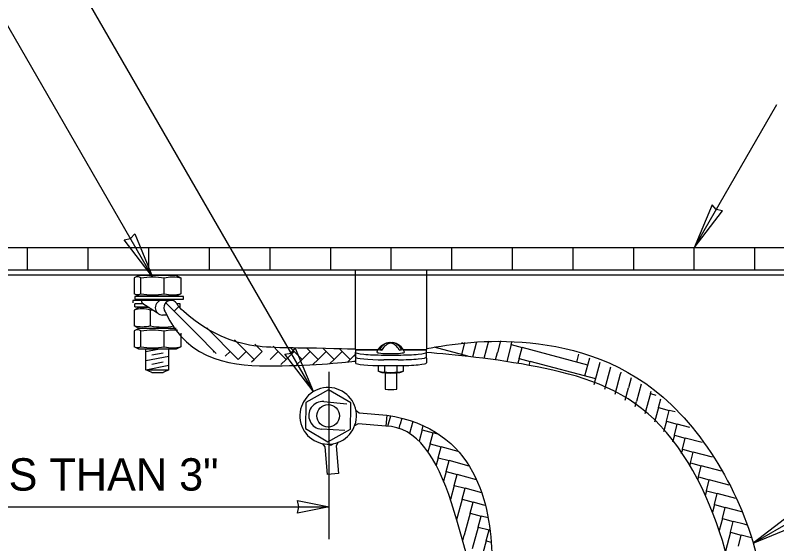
# Model space of a CAD drawing. Extents: x 99862 to 104211, y 98939 to 102076.
# Drawn here: x 100753.9 to 101130.8, y 100589.4 to 100850.7 of the extents above; entities that cross this region are included whole.
import ezdxf

# ---------------------------------------------------------------- set-up
doc = ezdxf.new("R2010")
doc.units = 0
for name, color, linetype in [('Level 1', 7, 'Continuous'), ('Level 11', 7, 'Continuous'), ('Level 15', 7, 'Continuous'), ('Level 20', 7, 'Continuous'), ('Level 22', 7, 'Continuous'), ('Level 3', 7, 'Continuous'), ('Level 4', 7, 'Continuous'), ('Level 6', 7, 'Continuous'), ('Level 8', 7, 'Continuous'), ('Level 9', 7, 'Continuous')]:
    doc.layers.add(name, color=color, linetype=linetype)

msp = doc.modelspace()

# ---------------------------------------------------------------- linework, layer by layer
at = {"layer": 'Level 1'}
for p, q in [((100609.83, 100722.28), (100942.61, 100722.28)), ((100941.81, 100722.28), (101395.03, 100722.28))]:
    msp.add_line(p, q, dxfattribs=at)
at = {"layer": 'Level 11'}
for p, q in [((100935.5, 100685.41), (100934.2, 100685.32)), ((100943.84, 100685.41), (100945.13, 100685.32)), ((100936.9, 100673.89), (100936.9, 100665.89)), ((100942.77, 100665.89), (100942.77, 100673.89))]:
    msp.add_line(p, q, dxfattribs=at)
for start, end in [(78.6144, 160.1915), (19.8085, 84.0285)]:
    msp.add_arc((100939.67, 100681.62), 7.26, start, end, dxfattribs=at)
for centre, major_axis, ratio, start_param, end_param in [((100939.08, 100681.7), (-0.98, -7.12), 0.811046, 3.337919, 4.294117), ((100940.24, 100681.55), (0.98, 7.12), 0.811046, 0.266133, 1.152722), ((100939.09, 100681.55), (-0.98, 7.12), 0.811046, 5.130463, 6.017052), ((100940.25, 100681.7), (0.98, -7.12), 0.811046, 1.989068, 2.945267), ((100939.67, 100684.06), (-6.83, 0), 0.097506, 6.248079, 7.853982), ((100939.67, 100685.58), (6.07, 0), 0.097506, 3.592518, 3.924478), ((100939.67, 100684.06), (-6.83, 0), 0.097506, 1.570796, 3.176699), ((100939.67, 100685.58), (-6.07, 0), 0.097506, 2.358707, 2.690667), ((100939.83, 100665.89), (-2.93, 0), 0.097506, 6.283185, 9.424778)]:
    msp.add_ellipse(centre, major_axis=major_axis, ratio=ratio, start_param=start_param, end_param=end_param, dxfattribs=at)
at = {"layer": 'Level 15'}
for p, q in [((100901.25, 100664.76), (100759.32, 100910.59)), ((100821.85, 100721.4), (100748.39, 100848.63)), ((101089.96, 100735.77), (101130.81, 100806.52)), ((100909.25, 100591.65), (100909.25, 100674.45)), ((101119.16, 100589.63), (101175.45, 100622.13)), ((100609.83, 100607.65), (100909.25, 100607.65))]:
    msp.add_line(p, q, dxfattribs=at)
for points in [[(101089.96, 100735.77), (101103.96, 100754.04), (101100.85, 100754.62), (101098.79, 100757.03)], [(100821.85, 100721.4), (100807.85, 100739.68), (100810.96, 100740.26), (100813.02, 100742.66)], [(100901.25, 100664.76), (100887.25, 100683.04), (100890.36, 100683.62), (100892.42, 100686.03)], [(100909.25, 100607.65), (100893.52, 100604.57), (100894.25, 100607.65), (100893.52, 100610.74)], [(101119.16, 100589.63), (101140.42, 100598.46), (101138.01, 100600.52), (101137.44, 100603.63)]]:
    msp.add_lwpolyline(points, close=True, dxfattribs=at)
at = {"layer": 'Level 22'}
msp.add_arc((100908.75, 100652.63), 14.01, 9.587, 9.5761, dxfattribs=at)
at = {"layer": 'Level 3'}
for p, q in [((100609.93, 100724.78), (101689.72, 100724.79)), ((100813.01, 100706.56), (100813.01, 100707.99)), ((100817.37, 100707.99), (100813.01, 100707.99)), ((100835.49, 100707.99), (100834, 100707.99)), ((100835.49, 100706.56), (100835.49, 100707.99)), ((100818.54, 100675.44), (100818.54, 100685.55)), ((100829.94, 100675.44), (100829.94, 100685.55)), ((100818.54, 100675.44), (100829.94, 100675.44)), ((100821.39, 100674.02), (100827.09, 100674.02))]:
    msp.add_line(p, q, dxfattribs=at)
msp.add_lwpolyline([(100837.14, 100711.67), (100812.99, 100711.67), (100812.99, 100710.24), (100837.14, 100710.24)], close=True, dxfattribs=at)
for points in [[(100813.01, 100706.56), (100819.55, 100706.56)], [(100834.94, 100706.56), (100835.49, 100706.56)], [(100818.54, 100684.4), (100824.4, 100685.55)], [(100818.54, 100679.92), (100829.94, 100682.16)], [(100821.39, 100682.72), (100827.09, 100683.84)], [(100821.39, 100678.24), (100827.09, 100679.36)], [(100818.54, 100675.44), (100829.94, 100677.68)], [(100821.39, 100674.02), (100818.54, 100675.44)], [(100829.94, 100675.44), (100827.09, 100674.02)]]:
    msp.add_lwpolyline(points, dxfattribs=at)
msp.add_circle((100908.75, 100652.63), 5.55, dxfattribs=at)
at = {"layer": 'Level 4'}
for p, q in [((101689.83, 100735.77), (100609.83, 100735.77)), ((100759.83, 100735.77), (100759.83, 100724.78)), ((100789.83, 100735.77), (100789.83, 100724.78)), ((100819.83, 100735.77), (100819.83, 100724.79)), ((100849.83, 100735.77), (100849.83, 100724.79)), ((100879.83, 100735.77), (100879.83, 100724.79)), ((100909.83, 100735.77), (100909.83, 100724.79)), ((100939.83, 100735.77), (100939.83, 100724.63)), ((100969.83, 100735.77), (100969.83, 100724.79)), ((100999.83, 100735.77), (100999.83, 100724.79)), ((101029.83, 100735.77), (101029.83, 100724.79)), ((101059.83, 100735.77), (101059.83, 100724.79)), ((101089.83, 100735.77), (101089.83, 100724.79)), ((101119.83, 100735.77), (101119.83, 100724.79)), ((100812.73, 100720.82), (100812.72, 100713)), ((100815.03, 100722.05), (100812.73, 100720.82)), ((100833.46, 100722.05), (100815.03, 100722.05)), ((100816.04, 100713), (100816.04, 100720.82)), ((100827.65, 100713), (100827.65, 100720.82)), ((100833.46, 100722.05), (100835.76, 100720.82)), ((100835.75, 100720.82), (100835.75, 100713)), ((100815.02, 100711.76), (100812.72, 100713)), ((100812.72, 100713), (100812.72, 100713)), ((100835.75, 100713), (100833.44, 100711.76)), ((100833.44, 100711.76), (100815.02, 100711.76)), ((100812.74, 100704.91), (100812.73, 100697.09)), ((100815.04, 100706.14), (100812.74, 100704.91)), ((100820.19, 100706.14), (100815.04, 100706.14)), ((100820.83, 100697.09), (100820.83, 100704.91)), ((100815.03, 100695.86), (100812.73, 100697.09)), ((100812.73, 100697.09), (100812.73, 100697.09)), ((100812.73, 100694.62), (100812.72, 100686.8)), ((100815.03, 100695.86), (100812.73, 100694.62)), ((100833.44, 100695.86), (100815.03, 100695.86)), ((100833.44, 100695.86), (100815.03, 100695.86)), ((100816.04, 100686.8), (100816.04, 100694.62)), ((100827.65, 100686.8), (100827.65, 100694.62)), ((100835.75, 100693.51), (100835.75, 100686.8)), ((100815.02, 100685.57), (100812.72, 100686.8)), ((100812.72, 100686.8), (100812.72, 100686.8)), ((100835.75, 100686.8), (100833.44, 100685.57)), ((100833.44, 100685.57), (100815.02, 100685.57))]:
    msp.add_line(p, q, dxfattribs=at)
msp.add_lwpolyline([(100919.99, 100657.49), (100920, 100658.97), (100908.89, 100665.54), (100897.64, 100659.2), (100897.51, 100646.29), (100908.62, 100639.72), (100919.87, 100646.06), (100919.99, 100657.49)], dxfattribs=at)
for points, degree in [([(100816.04, 100720.82), (100815.49, 100721.18), (100814.93, 100721.4), (100813.82, 100721.4), (100813.27, 100721.18), (100812.72, 100720.82)], 3), ([(100816.04, 100720.82), (100817.98, 100721.18), (100821.85, 100721.62), (100825.72, 100721.18), (100827.65, 100720.82)], 3), ([(100827.65, 100720.82), (100829.04, 100721.18), (100831.23, 100721.53), (100833.43, 100721.32), (100835.76, 100720.82)], 3), ([(100816.04, 100713), (100815.49, 100712.64), (100814.93, 100712.41), (100813.82, 100712.41), (100813.27, 100712.64), (100812.72, 100713)], 3), ([(100816.04, 100713), (100817.98, 100712.63), (100821.85, 100712.19), (100825.72, 100712.63), (100827.65, 100713)], 3), ([(100827.65, 100713), (100829.04, 100712.63), (100831.8, 100712.19), (100834.56, 100712.63), (100835.75, 100713)], 3), ([(100820.83, 100704.91), (100819.45, 100705.27), (100816.68, 100705.71), (100813.92, 100705.27), (100812.74, 100704.91)], 3), ([(100820.83, 100704.91), (100821.15, 100704.97), (100821.48, 100705.03), (100821.81, 100705.08)], 2), ([(100820.83, 100697.09), (100819.45, 100696.73), (100816.68, 100696.29), (100813.92, 100696.73), (100812.73, 100697.09)], 3), ([(100820.83, 100697.09), (100822.76, 100696.73), (100826.62, 100696.29), (100830.47, 100696.72), (100832.39, 100697.08)], 3), ([(100816.04, 100694.62), (100815.49, 100694.98), (100814.93, 100695.21), (100813.82, 100695.21), (100813.27, 100694.98), (100812.72, 100694.62)], 3), ([(100816.04, 100694.62), (100817.98, 100694.99), (100821.85, 100695.43), (100825.72, 100694.99), (100827.65, 100694.62)], 3), ([(100827.65, 100694.62), (100829.04, 100694.99), (100831.25, 100695.34), (100833.46, 100695.13), (100834.25, 100694.98)], 3), ([(100816.04, 100686.8), (100815.49, 100686.44), (100814.93, 100686.22), (100813.82, 100686.22), (100813.27, 100686.44), (100812.72, 100686.8)], 3), ([(100816.04, 100686.8), (100817.98, 100686.44), (100821.85, 100686), (100825.72, 100686.44), (100827.65, 100686.8)], 3), ([(100827.65, 100686.8), (100829.04, 100686.44), (100831.8, 100686), (100834.56, 100686.44), (100835.75, 100686.8)], 3)]:
    msp.add_open_spline(points, degree=degree, dxfattribs=at)
at = {"layer": 'Level 6'}
for p, q in [((100922.24, 100684.06), (100922.24, 100683.07)), ((100922.24, 100683.07), (100922.24, 100683.04)), ((100922.24, 100683.04), (100922.24, 100682.83)), ((100922.24, 100682.83), (100922.24, 100681.18)), ((100957.43, 100683.07), (100957.43, 100684.06)), ((100957.43, 100683.04), (100957.43, 100683.07)), ((100957.43, 100682.83), (100957.43, 100683.04)), ((100957.43, 100681.18), (100957.43, 100682.83)), ((100922.24, 100681.18), (100922.24, 100678.85)), ((100957.43, 100681.18), (100957.43, 100678.85)), ((100933.68, 100674.64), (100933.68, 100677.61)), ((100936.31, 100677.48), (100943.35, 100677.48)), ((100936.76, 100674.12), (100936.76, 100677.51)), ((100942.91, 100674.12), (100942.91, 100677.51)), ((100945.98, 100674.64), (100945.98, 100677.61)), ((100934.78, 100674.25), (100935.37, 100674.09)), ((100944.29, 100674.09), (100944.89, 100674.25))]:
    msp.add_line(p, q, dxfattribs=at)
for centre, major_axis, start_param, end_param in [((100936.31, 100678.85), (-14.08, 0), 0, 1.570796), ((100943.35, 100678.85), (-14.08, 0), 1.570796, 3.141593), ((100939.83, 100674.26), (4.77, 0), 3.501396, 5.923382)]:
    msp.add_ellipse(centre, major_axis=major_axis, ratio=0.097506, start_param=start_param, end_param=end_param, dxfattribs=at)
for points in [[(100934.78, 100674.25), (100934.41, 100674.33), (100934.05, 100674.48), (100933.68, 100674.64)], [(100945.98, 100674.64), (100945.62, 100674.48), (100945.25, 100674.33), (100944.89, 100674.25)], [(100936.76, 100674.12), (100936.1, 100674.05), (100935.44, 100674.06), (100934.78, 100674.25)], [(100942.91, 100674.12), (100940.87, 100673.82), (100938.79, 100673.82), (100936.76, 100674.12)], [(100944.89, 100674.25), (100944.22, 100674.06), (100943.56, 100674.05), (100942.91, 100674.12)]]:
    msp.add_open_spline(points, degree=2, dxfattribs=at)
at = {"layer": 'Level 8'}
for p, q in [((100812.36, 100709.71), (100812.11, 100709.71)), ((100812.11, 100709.71), (100812.11, 100708.55)), ((100814.27, 100709.71), (100812.36, 100709.71)), ((100816.24, 100709.71), (100814.27, 100709.71)), ((100816.5, 100708.56), (100824.22, 100703.5)), ((100826.54, 100709.71), (100822.52, 100709.71)), ((100830.99, 100709.71), (100826.54, 100709.71)), ((100828.55, 100708.27), (100844.39, 100692.43)), ((100832.51, 100704.31), (100834.86, 100706.66)), ((100828.84, 100702.42), (100826.74, 100702.42)), ((100848.67, 100696.06), (100852.31, 100692.43)), ((100852.31, 100684.51), (100844.39, 100692.43)), ((100860.23, 100684.51), (100852.31, 100692.43)), ((100868.15, 100684.51), (100862.4, 100690.26)), ((100985.97, 100681.07), (100988.28, 100689.67)), ((100994.09, 100689.73), (100992.53, 100683.92)), ((100999.39, 100687.88), (100999.83, 100689.53)), ((100876.07, 100684.51), (100872.49, 100688.09)), ((100883.99, 100684.51), (100881.46, 100687.03)), ((100891.9, 100684.51), (100889.94, 100686.48)), ((100899.82, 100684.51), (100898.17, 100686.16)), ((100907.74, 100684.51), (100906.31, 100685.95)), ((100915.66, 100684.51), (100914.42, 100685.76)), ((100977.84, 100682.05), (100961.17, 100686.52)), ((100974.86, 100682.85), (100976.46, 100688.83)), ((100976.31, 100688.26), (100974.92, 100688.64)), ((100980.37, 100681.81), (100982.4, 100689.37)), ((100999.39, 100687.88), (100997.16, 100679.55)), ((100999.39, 100687.88), (101004.8, 100686.43)), ((100999.39, 100687.88), (100999.39, 100687.88)), ((101003.35, 100681.02), (101004.8, 100686.43)), ((101037.25, 100677.73), (101004.8, 100686.43)), ((100852.31, 100684.51), (100851.84, 100684.04)), ((100852.31, 100684.51), (100853.29, 100683.52)), ((100860.23, 100684.51), (100857.8, 100682.09)), ((100860.23, 100684.51), (100864.19, 100680.55)), ((100868.15, 100684.51), (100864.19, 100680.55)), ((100868.15, 100684.51), (100872.11, 100680.55)), ((100876.07, 100684.51), (100872.11, 100680.55)), ((100883.99, 100684.51), (100880.03, 100680.55)), ((100883.99, 100684.51), (100887.95, 100680.55)), ((100891.91, 100684.51), (100887.95, 100680.55)), ((100891.91, 100684.51), (100895.87, 100680.55)), ((100899.82, 100684.51), (100895.87, 100680.55)), ((100899.82, 100684.51), (100903.78, 100680.55)), ((100907.74, 100684.51), (100903.78, 100680.55)), ((100907.74, 100684.51), (100911.7, 100680.55)), ((100915.66, 100684.51), (100911.7, 100680.55)), ((100915.66, 100684.51), (100919.62, 100680.55)), ((100922.24, 100683.16), (100919.62, 100680.55)), ((100991.57, 100680.33), (100992.53, 100683.92)), ((100992.53, 100683.92), (100992.53, 100683.92)), ((101031.85, 100679.18), (101032.91, 100683.15)), ((100864.16, 100680.52), (100864.19, 100680.55)), ((100870.88, 100679.32), (100872.11, 100680.55)), ((100885.39, 100677.99), (100887.95, 100680.55)), ((100893.13, 100677.81), (100895.87, 100680.55)), ((100901.19, 100677.95), (100903.78, 100680.55)), ((100909.58, 100678.42), (100911.7, 100680.55)), ((100918.32, 100679.24), (100919.62, 100680.55)), ((101003.35, 100681.02), (101002.71, 100678.63)), ((101003.35, 100681.02), (101008.76, 100679.57)), ((101008.23, 100677.58), (101008.76, 100679.57)), ((101041.21, 100670.87), (101008.76, 100679.57)), ((101035.8, 100672.32), (101038.2, 100681.27)), ((101040.5, 100668.19), (101043.44, 100679.18)), ((101045.68, 100665.89), (101048.61, 100676.85)), ((101050.78, 100663.3), (101053.48, 100673.38)), ((101053.7, 100674.2), (101053.48, 100673.38)), ((101058.74, 100671.37), (101057.44, 100666.52)), ((101063.69, 100668.21), (101061.4, 100659.67)), ((101055.81, 100660.45), (101057.44, 100666.52)), ((101068.26, 100663.62), (101065.56, 100653.55)), ((101068.26, 100663.62), (101068.56, 100664.75)), ((101068.26, 100663.62), (101070.98, 100662.9)), ((100906.58, 100659.7), (100918.07, 100658.52)), ((101060.74, 100657.21), (101061.4, 100659.67)), ((101072.22, 100656.77), (101073.35, 100660.98)), ((101072.22, 100656.77), (101070.25, 100649.43)), ((101072.22, 100656.77), (101077.63, 100655.32)), ((100922.49, 100655.42), (100924.03, 100654.13)), ((100924.03, 100654.13), (100937.72, 100653.01)), ((100937.72, 100653.01), (100937.27, 100647.54)), ((100938.36, 100647.49), (100939.75, 100652.66)), ((101076.18, 100649.91), (101077.63, 100655.32)), ((101080.46, 100654.56), (101077.63, 100655.32)), ((100923.58, 100648.66), (100921.85, 100647.64)), ((100937.27, 100647.54), (100923.58, 100648.66)), ((100943.87, 100646.41), (100944.45, 100648.56)), ((100945.23, 100651.48), (100944.45, 100648.56)), ((100950.6, 100649.87), (100949, 100643.92)), ((101076.18, 100649.91), (101074.81, 100644.79)), ((101076.18, 100649.91), (101081.59, 100648.46)), ((101080.14, 100643.05), (101081.59, 100648.46)), ((101087.81, 100646.79), (101081.59, 100648.46)), ((100916.98, 100645.3), (100905.46, 100646.01)), ((100955.27, 100645.66), (100953.76, 100640.04)), ((100955.27, 100645.66), (100955.83, 100647.77)), ((100955.27, 100645.66), (100960.68, 100644.21)), ((100959.23, 100638.8), (100960.67, 100644.21)), ((100963.62, 100643.42), (100960.67, 100644.21)), ((101080.14, 100643.05), (101079.22, 100639.63)), ((101080.14, 100643.05), (101085.55, 100641.6)), ((101084.1, 100636.19), (101085.55, 100641.6)), ((101093.81, 100639.39), (101085.55, 100641.6)), ((100907.27, 100637.35), (100905.99, 100638.89)), ((100908.41, 100623.66), (100907.27, 100637.35)), ((100913.76, 100639.54), (100912.75, 100637.8)), ((100912.75, 100637.8), (100913.89, 100624.12)), ((100959.23, 100638.8), (100958.15, 100634.77)), ((100959.23, 100638.8), (100964.63, 100637.35)), ((100963.19, 100631.94), (100964.63, 100637.35)), ((100973.17, 100635.07), (100964.63, 100637.35)), ((101084.1, 100636.19), (101083.48, 100633.9)), ((101084.1, 100636.19), (101089.51, 100634.74)), ((101088.06, 100629.33), (101089.51, 100634.74)), ((101098.95, 100632.21), (101089.51, 100634.74)), ((100963.19, 100631.94), (100962.18, 100628.19)), ((100963.19, 100631.94), (100968.59, 100630.49)), ((100967.15, 100625.09), (100968.59, 100630.49)), ((100978.56, 100627.82), (100968.59, 100630.49)), ((101088.06, 100629.33), (101087.61, 100627.66)), ((101088.06, 100629.33), (101093.47, 100627.88)), ((101092.02, 100622.47), (101093.47, 100627.88)), ((101103.41, 100625.22), (101093.47, 100627.88)), ((100913.89, 100624.12), (100908.41, 100623.66)), ((100967.15, 100625.09), (100965.87, 100620.34)), ((100967.15, 100625.09), (100972.55, 100623.64)), ((100971.11, 100618.23), (100972.55, 100623.64)), ((100982.17, 100621.06), (100972.55, 100623.64)), ((101092.02, 100622.47), (101091.57, 100620.79)), ((101092.02, 100622.47), (101097.43, 100621.02)), ((100971.11, 100618.23), (100969.24, 100611.28)), ((100971.11, 100618.23), (100976.51, 100616.78)), ((101095.98, 100615.62), (101097.43, 100621.02)), ((101107.26, 100618.39), (101097.43, 100621.02)), ((100975.06, 100611.37), (100976.51, 100616.78)), ((100984.76, 100614.57), (100976.51, 100616.78)), ((101095.98, 100615.62), (101095.34, 100613.23)), ((101095.98, 100615.62), (101101.39, 100614.17)), ((101099.94, 100608.76), (101101.39, 100614.17)), ((101110.62, 100611.69), (101101.39, 100614.17)), ((100975.06, 100611.37), (100972.36, 100601.26)), ((100975.06, 100611.37), (100980.47, 100609.92)), ((100979.02, 100604.51), (100980.47, 100609.92)), ((100985.88, 100608.47), (100980.47, 100609.92)), ((100986.61, 100608.28), (100985.88, 100608.47)), ((101099.94, 100608.76), (101098.93, 100605)), ((101099.94, 100608.76), (101105.35, 100607.31)), ((101103.9, 100601.9), (101105.35, 100607.31)), ((101113.55, 100605.11), (101105.35, 100607.31)), ((100979.02, 100604.51), (100976.13, 100593.69)), ((100979.02, 100604.51), (100984.43, 100603.06)), ((100979.02, 100604.51), (100979.02, 100604.51)), ((100982.98, 100597.65), (100984.43, 100603.06)), ((100987.95, 100602.12), (100984.43, 100603.06)), ((101103.9, 100601.9), (101102.29, 100595.89)), ((101103.9, 100601.9), (101109.31, 100600.45)), ((101107.86, 100595.04), (101109.31, 100600.45)), ((101114.72, 100599), (101109.31, 100600.45)), ((101116.11, 100598.63), (101114.72, 100599)), ((100982.98, 100597.65), (100980.09, 100586.83)), ((100982.98, 100597.65), (100988.39, 100596.2)), ((100986.94, 100590.79), (100988.39, 100596.2)), ((100988.89, 100596.07), (100988.39, 100596.2)), ((100975.35, 100590.81), (100976.13, 100593.69)), ((101107.86, 100595.04), (101105.37, 100585.77)), ((101107.86, 100595.04), (101113.27, 100593.59)), ((101107.86, 100595.04), (101107.86, 100595.04)), ((101111.82, 100588.18), (101113.27, 100593.59)), ((101118.35, 100592.23), (101113.27, 100593.59)), ((100986.94, 100590.79), (100984.04, 100579.98)), ((100986.94, 100590.79), (100989.49, 100590.11))]:
    msp.add_line(p, q, dxfattribs=at)
msp.add_arc((100906.02, 100652.85), 6.87, 85.3109, 265.3109, dxfattribs=at)
for centre, major_axis, ratio, start_param, end_param in [((100826.74, 100706.06), (0, 3.65), 0.972495, 0.785398, 1.570796), ((100826.49, 100706.06), (0.25, 3.64), 0.886551, 0.061099, 0.846498), ((100830.99, 100706.06), (0, -3.65), 0.972495, 1.894042, 5.313344), ((100826.74, 100706.06), (0, 3.65), 0.972495, 1.570796, 3.141593), ((100892.56, 100655.77), (17.49, -17.48), 0.111087, 5.950489, 6.242362), ((100924.2, 100658.41), (-14.35, -20.13), 0.111087, 0.040823, 0.332697)]:
    msp.add_ellipse(centre, major_axis=major_axis, ratio=ratio, start_param=start_param, end_param=end_param, dxfattribs=at)
for points in [[(100816.24, 100709.71), (100816.29, 100709.55), (100816.34, 100709.38), (100816.43, 100709), (100816.47, 100708.79), (100816.5, 100708.55)], [(100822.52, 100709.71), (100822.23, 100709.71), (100821.66, 100709.71), (100820.58, 100709.71), (100818.74, 100709.71), (100817.23, 100709.71), (100816.24, 100709.71)], [(100922.24, 100685.55), (100919.55, 100685.63), (100892.49, 100686.34), (100859.42, 100686.34), (100838.53, 100702.36), (100834.35, 100707.22)], [(100828.06, 100704), (100839.66, 100678.72), (100885.4, 100675.62), (100918.97, 100679.29), (100922.24, 100679.7)], [(100957.43, 100685.85), (100969.13, 100688.05), (101004.77, 100693.69), (101082.42, 100672.12), (101138.16, 100565.85), (101105.88, 100478.97), (100986.25, 100528.69), (100972.45, 100616.68), (100952.65, 100647.27), (100937.27, 100647.54)], [(100937.72, 100653.01), (100982.26, 100646.2), (100995.93, 100570.97), (100980.26, 100528.28), (101068.89, 100474.17), (101112.45, 100523.7), (101110.96, 100583.9), (101074.6, 100660.56), (101012.34, 100678.81), (100970.27, 100682.99), (100957.43, 100683.88)]]:
    msp.add_open_spline(points, degree=3, dxfattribs=at)
at = {"layer": 'Level 9'}
for p, q in [((100957.43, 100724.63), (100922.24, 100724.63)), ((100922.24, 100722.28), (100922.24, 100724.63)), ((100957.43, 100724.63), (100957.43, 100685.44)), ((100922.24, 100722.28), (100957.43, 100722.28)), ((100922.24, 100685.44), (100922.24, 100722.28)), ((100922.24, 100685.44), (100922.24, 100685.2)), ((100922.24, 100685.44), (100933.5, 100685.44)), ((100922.24, 100685.2), (100922.24, 100684.06)), ((100922.24, 100685.2), (100933.35, 100685.2)), ((100922.24, 100681.73), (100922.24, 100684.06)), ((100936.31, 100682.69), (100943.35, 100682.69)), ((100945.84, 100685.44), (100957.43, 100685.44)), ((100945.98, 100685.2), (100957.43, 100685.2)), ((100957.43, 100685.2), (100957.43, 100685.44)), ((100957.43, 100684.06), (100957.43, 100685.2)), ((100957.43, 100681.73), (100957.43, 100684.06)), ((100943.35, 100680.35), (100936.31, 100680.35))]:
    msp.add_line(p, q, dxfattribs=at)
for centre, start_param, end_param in [((100936.31, 100684.06), 6.283185, 7.853982), ((100943.35, 100684.06), 1.570796, 3.141593), ((100936.31, 100681.73), 0, 1.570796), ((100943.35, 100681.73), 1.570796, 3.141593)]:
    msp.add_ellipse(centre, major_axis=(-14.08, 0), ratio=0.097506, start_param=start_param, end_param=end_param, dxfattribs=at)

# ---------------------------------------------------------------- texts
at = {"layer": 'Level 20'}
msp.add_text('NOT LESS THAN 3"', height=16, dxfattribs=at).set_placement((100659.02, 100615.65))

doc.saveas('drawing.dxf')
